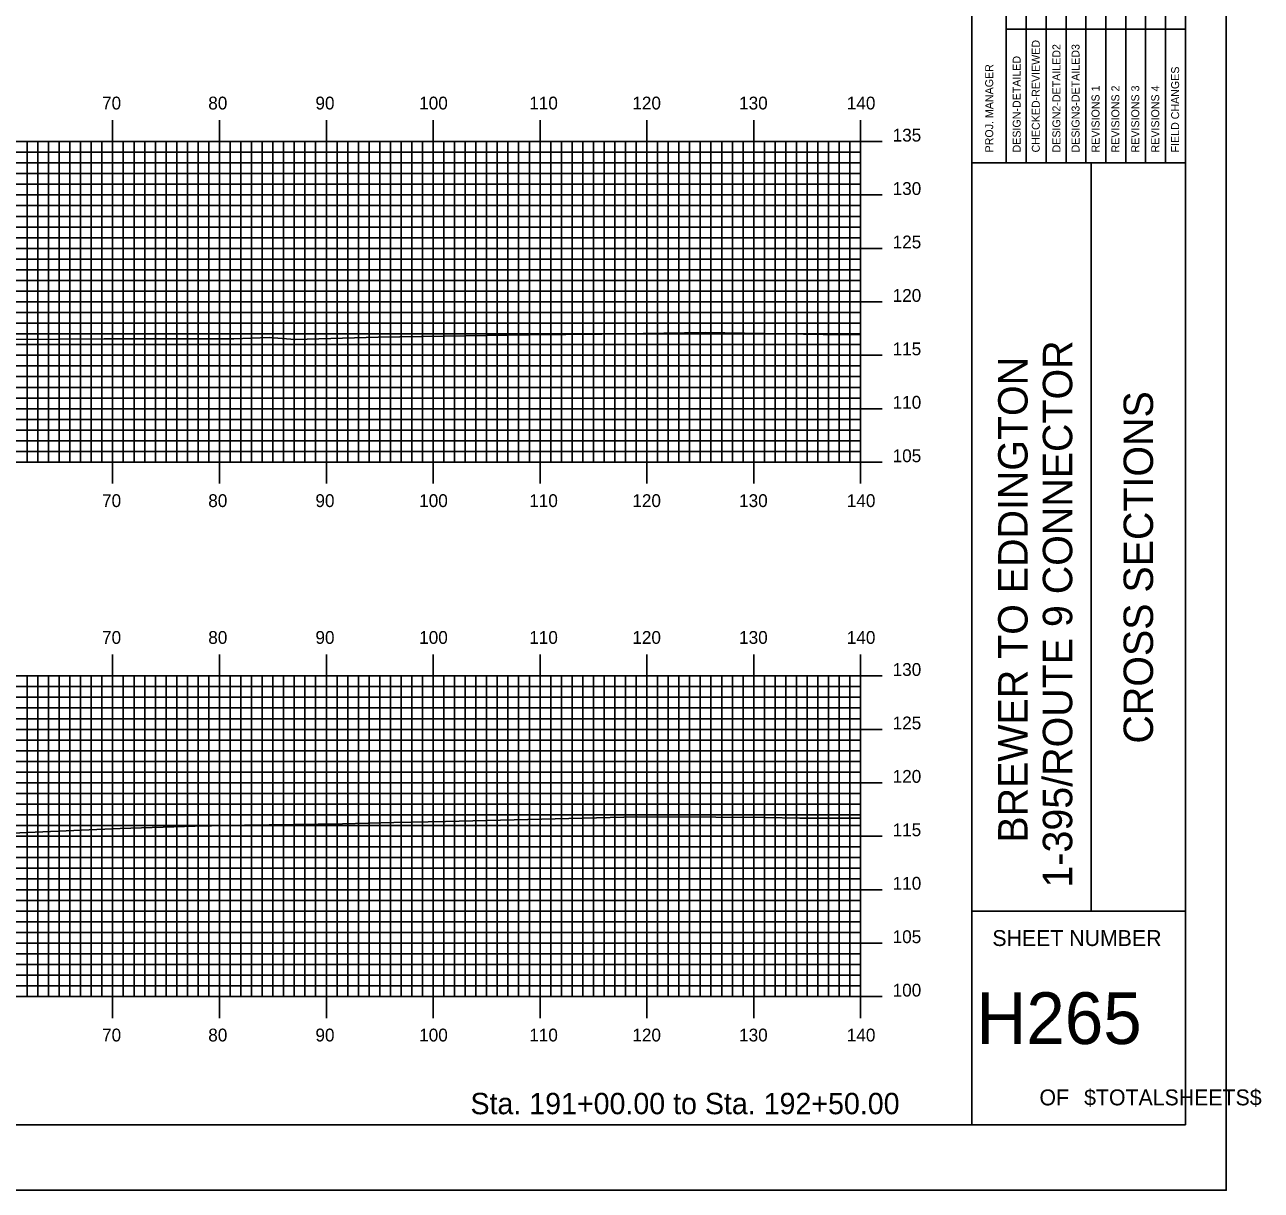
# Model space of a CAD drawing. Extents: x 1788550 to 1788893, y 442591 to 442811.
# Drawn here: x 1788777.4 to 1788893.1, y 442590.5 to 442699.6 of the extents above; entities that cross this region are included whole.
import ezdxf

# ---------------------------------------------------------------- set-up
doc = ezdxf.new("R2010")
doc.units = 0
for name, color, linetype in [('BORDER', 7, 'Continuous'), ('H_V ANNOTATION', 7, 'Continuous'), ('MAJOR', 7, 'Continuous'), ('MINOR', 7, 'Continuous'), ('PLOT BOUNDARY', 7, 'Continuous'), ('S_Roadway_Centerline', 7, 'Continuous')]:
    doc.layers.add(name, color=color, linetype=linetype)

msp = doc.modelspace()

# ---------------------------------------------------------------- linework, layer by layer
at = {"layer": 'BORDER'}
for p, q in [((1788866.04, 442596.67), (1788866.04, 442806.67)), ((1788866.04, 442686.67), (1788886.04, 442686.67)), ((1788877.23, 442616.67), (1788877.23, 442686.67)), ((1788866.04, 442616.67), (1788886.04, 442616.67))]:
    msp.add_line(p, q, dxfattribs=at)
msp.add_lwpolyline([(1788566.04, 442596.67), (1788886.04, 442596.67), (1788886.04, 442806.67), (1788566.04, 442806.67)], close=True, dxfattribs=at)
for points in [[(1788871.14, 442686.68), (1788871.14, 442721.67)], [(1788873, 442721.67), (1788873, 442686.68)], [(1788874.87, 442686.68), (1788874.87, 442721.67)], [(1788876.73, 442686.68), (1788876.73, 442721.67)], [(1788878.59, 442686.68), (1788878.59, 442721.67)], [(1788880.46, 442686.68), (1788880.46, 442721.67)], [(1788882.32, 442686.68), (1788882.32, 442721.67)], [(1788884.18, 442686.68), (1788884.18, 442721.67)], [(1788869.27, 442686.68), (1788869.27, 442720.26)], [(1788869.27, 442699.17), (1788886.04, 442699.17)]]:
    msp.add_lwpolyline(points, dxfattribs=at)
at = {"layer": 'MAJOR'}
for p, q in [((1788785.64, 442690.67), (1788785.64, 442688.67)), ((1788795.64, 442690.67), (1788795.64, 442688.67)), ((1788805.64, 442690.67), (1788805.64, 442688.67)), ((1788815.64, 442690.67), (1788815.64, 442688.67)), ((1788825.64, 442690.67), (1788825.64, 442688.67)), ((1788835.64, 442690.67), (1788835.64, 442688.67)), ((1788845.64, 442690.67), (1788845.64, 442688.67)), ((1788855.64, 442690.67), (1788855.64, 442688.67)), ((1788575.64, 442688.67), (1788855.64, 442688.67)), ((1788575.64, 442688.67), (1788855.64, 442688.67)), ((1788785.64, 442658.67), (1788785.64, 442688.67)), ((1788795.64, 442658.67), (1788795.64, 442688.67)), ((1788805.64, 442658.67), (1788805.64, 442688.67)), ((1788815.64, 442658.67), (1788815.64, 442688.67)), ((1788825.64, 442658.67), (1788825.64, 442688.67)), ((1788835.64, 442658.67), (1788835.64, 442688.67)), ((1788845.64, 442658.67), (1788845.64, 442688.67)), ((1788857.65, 442688.67), (1788853.64, 442688.67)), ((1788855.64, 442658.67), (1788855.64, 442688.67)), ((1788855.64, 442658.67), (1788855.64, 442688.67)), ((1788575.64, 442683.67), (1788855.64, 442683.67)), ((1788857.65, 442683.67), (1788853.64, 442683.67)), ((1788575.64, 442678.67), (1788855.64, 442678.67)), ((1788857.65, 442678.67), (1788853.64, 442678.67)), ((1788575.64, 442673.67), (1788855.64, 442673.67)), ((1788857.65, 442673.67), (1788853.64, 442673.67)), ((1788575.64, 442668.67), (1788855.64, 442668.67)), ((1788857.65, 442668.67), (1788853.64, 442668.67)), ((1788575.64, 442663.67), (1788855.64, 442663.67)), ((1788857.65, 442663.67), (1788853.64, 442663.67)), ((1788575.64, 442658.67), (1788855.64, 442658.67)), ((1788575.64, 442658.67), (1788855.64, 442658.67)), ((1788785.64, 442656.66), (1788785.64, 442658.67)), ((1788795.64, 442656.66), (1788795.64, 442658.67)), ((1788805.64, 442656.66), (1788805.64, 442658.67)), ((1788815.64, 442656.66), (1788815.64, 442658.67)), ((1788825.64, 442656.66), (1788825.64, 442658.67)), ((1788835.64, 442656.66), (1788835.64, 442658.67)), ((1788845.64, 442656.66), (1788845.64, 442658.67)), ((1788857.65, 442658.67), (1788853.64, 442658.67)), ((1788855.64, 442656.66), (1788855.64, 442658.67)), ((1788785.64, 442640.67), (1788785.64, 442638.67)), ((1788795.64, 442640.67), (1788795.64, 442638.67)), ((1788805.64, 442640.67), (1788805.64, 442638.67)), ((1788815.64, 442640.67), (1788815.64, 442638.67)), ((1788825.64, 442640.67), (1788825.64, 442638.67)), ((1788835.64, 442640.67), (1788835.64, 442638.67)), ((1788845.64, 442640.67), (1788845.64, 442638.67)), ((1788855.64, 442640.67), (1788855.64, 442638.67)), ((1788575.64, 442638.67), (1788855.64, 442638.67)), ((1788575.64, 442638.67), (1788855.64, 442638.67)), ((1788785.64, 442608.67), (1788785.64, 442638.67)), ((1788795.64, 442608.67), (1788795.64, 442638.67)), ((1788805.64, 442608.67), (1788805.64, 442638.67)), ((1788815.64, 442608.67), (1788815.64, 442638.67)), ((1788825.64, 442608.67), (1788825.64, 442638.67)), ((1788835.64, 442608.67), (1788835.64, 442638.67)), ((1788845.64, 442608.67), (1788845.64, 442638.67)), ((1788857.65, 442638.67), (1788853.64, 442638.67)), ((1788855.64, 442608.67), (1788855.64, 442638.67)), ((1788855.64, 442608.67), (1788855.64, 442638.67)), ((1788575.64, 442633.67), (1788855.64, 442633.67)), ((1788857.65, 442633.67), (1788853.64, 442633.67)), ((1788575.64, 442628.67), (1788855.64, 442628.67)), ((1788857.65, 442628.67), (1788853.64, 442628.67)), ((1788575.64, 442623.67), (1788855.64, 442623.67)), ((1788857.65, 442623.67), (1788853.64, 442623.67)), ((1788575.64, 442618.67), (1788855.64, 442618.67)), ((1788857.65, 442618.67), (1788853.64, 442618.67)), ((1788575.64, 442613.67), (1788855.64, 442613.67)), ((1788857.65, 442613.67), (1788853.64, 442613.67)), ((1788575.64, 442608.67), (1788855.64, 442608.67)), ((1788575.64, 442608.67), (1788855.64, 442608.67)), ((1788785.64, 442606.66), (1788785.64, 442608.67)), ((1788795.64, 442606.66), (1788795.64, 442608.67)), ((1788805.64, 442606.66), (1788805.64, 442608.67)), ((1788815.64, 442606.66), (1788815.64, 442608.67)), ((1788825.64, 442606.66), (1788825.64, 442608.67)), ((1788835.64, 442606.66), (1788835.64, 442608.67)), ((1788845.64, 442606.66), (1788845.64, 442608.67)), ((1788857.65, 442608.67), (1788853.64, 442608.67)), ((1788855.64, 442606.66), (1788855.64, 442608.67))]:
    msp.add_line(p, q, dxfattribs=at)
at = {"layer": 'MINOR'}
for p, q in [((1788777.64, 442658.67), (1788777.64, 442688.67)), ((1788778.64, 442658.67), (1788778.64, 442688.67)), ((1788779.64, 442658.67), (1788779.64, 442688.67)), ((1788780.64, 442658.67), (1788780.64, 442688.67)), ((1788781.64, 442658.67), (1788781.64, 442688.67)), ((1788782.64, 442658.67), (1788782.64, 442688.67)), ((1788783.64, 442658.67), (1788783.64, 442688.67)), ((1788784.64, 442658.67), (1788784.64, 442688.67)), ((1788786.64, 442658.67), (1788786.64, 442688.67)), ((1788787.64, 442658.67), (1788787.64, 442688.67)), ((1788788.64, 442658.67), (1788788.64, 442688.67)), ((1788789.64, 442658.67), (1788789.64, 442688.67)), ((1788790.64, 442658.67), (1788790.64, 442688.67)), ((1788791.64, 442658.67), (1788791.64, 442688.67)), ((1788792.64, 442658.67), (1788792.64, 442688.67)), ((1788793.64, 442658.67), (1788793.64, 442688.67)), ((1788794.64, 442658.67), (1788794.64, 442688.67)), ((1788796.64, 442658.67), (1788796.64, 442688.67)), ((1788797.64, 442658.67), (1788797.64, 442688.67)), ((1788798.64, 442658.67), (1788798.64, 442688.67)), ((1788799.64, 442658.67), (1788799.64, 442688.67)), ((1788800.64, 442658.67), (1788800.64, 442688.67)), ((1788801.64, 442658.67), (1788801.64, 442688.67)), ((1788802.64, 442658.67), (1788802.64, 442688.67)), ((1788803.64, 442658.67), (1788803.64, 442688.67)), ((1788804.64, 442658.67), (1788804.64, 442688.67)), ((1788806.64, 442658.67), (1788806.64, 442688.67)), ((1788807.64, 442658.67), (1788807.64, 442688.67)), ((1788808.64, 442658.67), (1788808.64, 442688.67)), ((1788809.64, 442658.67), (1788809.64, 442688.67)), ((1788810.64, 442658.67), (1788810.64, 442688.67)), ((1788811.64, 442658.67), (1788811.64, 442688.67)), ((1788812.64, 442658.67), (1788812.64, 442688.67)), ((1788813.64, 442658.67), (1788813.64, 442688.67)), ((1788814.64, 442658.67), (1788814.64, 442688.67)), ((1788816.64, 442658.67), (1788816.64, 442688.67)), ((1788817.64, 442658.67), (1788817.64, 442688.67)), ((1788818.64, 442658.67), (1788818.64, 442688.67)), ((1788819.64, 442658.67), (1788819.64, 442688.67)), ((1788820.64, 442658.67), (1788820.64, 442688.67)), ((1788821.64, 442658.67), (1788821.64, 442688.67)), ((1788822.64, 442658.67), (1788822.64, 442688.67)), ((1788823.64, 442658.67), (1788823.64, 442688.67)), ((1788824.64, 442658.67), (1788824.64, 442688.67)), ((1788826.64, 442658.67), (1788826.64, 442688.67)), ((1788827.64, 442658.67), (1788827.64, 442688.67)), ((1788828.64, 442658.67), (1788828.64, 442688.67)), ((1788829.64, 442658.67), (1788829.64, 442688.67)), ((1788830.64, 442658.67), (1788830.64, 442688.67)), ((1788831.64, 442658.67), (1788831.64, 442688.67)), ((1788832.64, 442658.67), (1788832.64, 442688.67)), ((1788833.64, 442658.67), (1788833.64, 442688.67)), ((1788834.64, 442658.67), (1788834.64, 442688.67)), ((1788836.64, 442658.67), (1788836.64, 442688.67)), ((1788837.64, 442658.67), (1788837.64, 442688.67)), ((1788838.64, 442658.67), (1788838.64, 442688.67)), ((1788839.64, 442658.67), (1788839.64, 442688.67)), ((1788840.64, 442658.67), (1788840.64, 442688.67)), ((1788841.64, 442658.67), (1788841.64, 442688.67)), ((1788842.64, 442658.67), (1788842.64, 442688.67)), ((1788843.64, 442658.67), (1788843.64, 442688.67)), ((1788844.64, 442658.67), (1788844.64, 442688.67)), ((1788846.64, 442658.67), (1788846.64, 442688.67)), ((1788847.64, 442658.67), (1788847.64, 442688.67)), ((1788848.64, 442658.67), (1788848.64, 442688.67)), ((1788849.64, 442658.67), (1788849.64, 442688.67)), ((1788850.64, 442658.67), (1788850.64, 442688.67)), ((1788851.64, 442658.67), (1788851.64, 442688.67)), ((1788852.64, 442658.67), (1788852.64, 442688.67)), ((1788853.64, 442658.67), (1788853.64, 442688.67)), ((1788854.64, 442658.67), (1788854.64, 442688.67)), ((1788575.64, 442687.67), (1788855.64, 442687.67)), ((1788855.64, 442687.67), (1788853.64, 442687.67)), ((1788575.64, 442686.67), (1788855.64, 442686.67)), ((1788855.64, 442686.67), (1788853.64, 442686.67)), ((1788575.64, 442685.67), (1788855.64, 442685.67)), ((1788855.64, 442685.67), (1788853.64, 442685.67)), ((1788575.64, 442684.67), (1788855.64, 442684.67)), ((1788855.64, 442684.67), (1788853.64, 442684.67)), ((1788575.64, 442682.67), (1788855.64, 442682.67)), ((1788855.64, 442682.67), (1788853.64, 442682.67)), ((1788575.64, 442681.67), (1788855.64, 442681.67)), ((1788855.64, 442681.67), (1788853.64, 442681.67)), ((1788575.64, 442680.67), (1788855.64, 442680.67)), ((1788855.64, 442680.67), (1788853.64, 442680.67)), ((1788575.64, 442679.67), (1788855.64, 442679.67)), ((1788855.64, 442679.67), (1788853.64, 442679.67)), ((1788575.64, 442677.67), (1788855.64, 442677.67)), ((1788855.64, 442677.67), (1788853.64, 442677.67)), ((1788575.64, 442676.67), (1788855.64, 442676.67)), ((1788855.64, 442676.67), (1788853.64, 442676.67)), ((1788575.64, 442675.67), (1788855.64, 442675.67)), ((1788575.64, 442674.67), (1788855.64, 442674.67)), ((1788855.64, 442675.67), (1788853.64, 442675.67)), ((1788855.64, 442674.67), (1788853.64, 442674.67)), ((1788575.64, 442672.67), (1788855.64, 442672.67)), ((1788855.64, 442672.67), (1788853.64, 442672.67)), ((1788575.64, 442671.67), (1788855.64, 442671.67)), ((1788855.64, 442671.67), (1788853.64, 442671.67)), ((1788575.64, 442670.67), (1788855.64, 442670.67)), ((1788855.64, 442670.67), (1788853.64, 442670.67)), ((1788575.64, 442669.67), (1788855.64, 442669.67)), ((1788855.64, 442669.67), (1788853.64, 442669.67)), ((1788575.64, 442667.67), (1788855.64, 442667.67)), ((1788855.64, 442667.67), (1788853.64, 442667.67)), ((1788575.64, 442666.67), (1788855.64, 442666.67)), ((1788855.64, 442666.67), (1788853.64, 442666.67)), ((1788575.64, 442665.67), (1788855.64, 442665.67)), ((1788855.64, 442665.67), (1788853.64, 442665.67)), ((1788575.64, 442664.67), (1788855.64, 442664.67)), ((1788855.64, 442664.67), (1788853.64, 442664.67)), ((1788575.64, 442662.67), (1788855.64, 442662.67)), ((1788855.64, 442662.67), (1788853.64, 442662.67)), ((1788575.64, 442661.67), (1788855.64, 442661.67)), ((1788575.64, 442660.67), (1788855.64, 442660.67)), ((1788855.64, 442661.67), (1788853.64, 442661.67)), ((1788855.64, 442660.67), (1788853.64, 442660.67)), ((1788575.64, 442659.67), (1788855.64, 442659.67)), ((1788855.64, 442659.67), (1788853.64, 442659.67)), ((1788777.64, 442608.67), (1788777.64, 442638.67)), ((1788778.64, 442608.67), (1788778.64, 442638.67)), ((1788779.64, 442608.67), (1788779.64, 442638.67)), ((1788780.64, 442608.67), (1788780.64, 442638.67)), ((1788781.64, 442608.67), (1788781.64, 442638.67)), ((1788782.64, 442608.67), (1788782.64, 442638.67)), ((1788783.64, 442608.67), (1788783.64, 442638.67)), ((1788784.64, 442608.67), (1788784.64, 442638.67)), ((1788786.64, 442608.67), (1788786.64, 442638.67)), ((1788787.64, 442608.67), (1788787.64, 442638.67)), ((1788788.64, 442608.67), (1788788.64, 442638.67)), ((1788789.64, 442608.67), (1788789.64, 442638.67)), ((1788790.64, 442608.67), (1788790.64, 442638.67)), ((1788791.64, 442608.67), (1788791.64, 442638.67)), ((1788792.64, 442608.67), (1788792.64, 442638.67)), ((1788793.64, 442608.67), (1788793.64, 442638.67)), ((1788794.64, 442608.67), (1788794.64, 442638.67)), ((1788796.64, 442608.67), (1788796.64, 442638.67)), ((1788797.64, 442608.67), (1788797.64, 442638.67)), ((1788798.64, 442608.67), (1788798.64, 442638.67)), ((1788799.64, 442608.67), (1788799.64, 442638.67)), ((1788800.64, 442608.67), (1788800.64, 442638.67)), ((1788801.64, 442608.67), (1788801.64, 442638.67)), ((1788802.64, 442608.67), (1788802.64, 442638.67)), ((1788803.64, 442608.67), (1788803.64, 442638.67)), ((1788804.64, 442608.67), (1788804.64, 442638.67)), ((1788806.64, 442608.67), (1788806.64, 442638.67)), ((1788807.64, 442608.67), (1788807.64, 442638.67)), ((1788808.64, 442608.67), (1788808.64, 442638.67)), ((1788809.64, 442608.67), (1788809.64, 442638.67)), ((1788810.64, 442608.67), (1788810.64, 442638.67)), ((1788811.64, 442608.67), (1788811.64, 442638.67)), ((1788812.64, 442608.67), (1788812.64, 442638.67)), ((1788813.64, 442608.67), (1788813.64, 442638.67)), ((1788814.64, 442608.67), (1788814.64, 442638.67)), ((1788816.64, 442608.67), (1788816.64, 442638.67)), ((1788817.64, 442608.67), (1788817.64, 442638.67)), ((1788818.64, 442608.67), (1788818.64, 442638.67)), ((1788819.64, 442608.67), (1788819.64, 442638.67)), ((1788820.64, 442608.67), (1788820.64, 442638.67)), ((1788821.64, 442608.67), (1788821.64, 442638.67)), ((1788822.64, 442608.67), (1788822.64, 442638.67)), ((1788823.64, 442608.67), (1788823.64, 442638.67)), ((1788824.64, 442608.67), (1788824.64, 442638.67)), ((1788826.64, 442608.67), (1788826.64, 442638.67)), ((1788827.64, 442608.67), (1788827.64, 442638.67)), ((1788828.64, 442608.67), (1788828.64, 442638.67)), ((1788829.64, 442608.67), (1788829.64, 442638.67)), ((1788830.64, 442608.67), (1788830.64, 442638.67)), ((1788831.64, 442608.67), (1788831.64, 442638.67)), ((1788832.64, 442608.67), (1788832.64, 442638.67)), ((1788833.64, 442608.67), (1788833.64, 442638.67)), ((1788834.64, 442608.67), (1788834.64, 442638.67)), ((1788836.64, 442608.67), (1788836.64, 442638.67)), ((1788837.64, 442608.67), (1788837.64, 442638.67)), ((1788838.64, 442608.67), (1788838.64, 442638.67)), ((1788839.64, 442608.67), (1788839.64, 442638.67)), ((1788840.64, 442608.67), (1788840.64, 442638.67)), ((1788841.64, 442608.67), (1788841.64, 442638.67)), ((1788842.64, 442608.67), (1788842.64, 442638.67)), ((1788843.64, 442608.67), (1788843.64, 442638.67)), ((1788844.64, 442608.67), (1788844.64, 442638.67)), ((1788846.64, 442608.67), (1788846.64, 442638.67)), ((1788847.64, 442608.67), (1788847.64, 442638.67)), ((1788848.64, 442608.67), (1788848.64, 442638.67)), ((1788849.64, 442608.67), (1788849.64, 442638.67)), ((1788850.64, 442608.67), (1788850.64, 442638.67)), ((1788851.64, 442608.67), (1788851.64, 442638.67)), ((1788852.64, 442608.67), (1788852.64, 442638.67)), ((1788853.64, 442608.67), (1788853.64, 442638.67)), ((1788854.64, 442608.67), (1788854.64, 442638.67)), ((1788575.64, 442637.67), (1788855.64, 442637.67)), ((1788855.64, 442637.67), (1788853.64, 442637.67)), ((1788575.64, 442636.67), (1788855.64, 442636.67)), ((1788855.64, 442636.67), (1788853.64, 442636.67)), ((1788575.64, 442635.67), (1788855.64, 442635.67)), ((1788855.64, 442635.67), (1788853.64, 442635.67)), ((1788575.64, 442634.67), (1788855.64, 442634.67)), ((1788855.64, 442634.67), (1788853.64, 442634.67)), ((1788575.64, 442632.67), (1788855.64, 442632.67)), ((1788855.64, 442632.67), (1788853.64, 442632.67)), ((1788575.64, 442631.67), (1788855.64, 442631.67)), ((1788575.64, 442630.67), (1788855.64, 442630.67)), ((1788855.64, 442631.67), (1788853.64, 442631.67)), ((1788855.64, 442630.67), (1788853.64, 442630.67)), ((1788575.64, 442629.67), (1788855.64, 442629.67)), ((1788855.64, 442629.67), (1788853.64, 442629.67)), ((1788575.64, 442627.67), (1788855.64, 442627.67)), ((1788855.64, 442627.67), (1788853.64, 442627.67)), ((1788575.64, 442626.67), (1788855.64, 442626.67)), ((1788855.64, 442626.67), (1788853.64, 442626.67)), ((1788575.64, 442625.67), (1788855.64, 442625.67)), ((1788855.64, 442625.67), (1788853.64, 442625.67)), ((1788575.64, 442624.67), (1788855.64, 442624.67)), ((1788855.64, 442624.67), (1788853.64, 442624.67)), ((1788575.64, 442622.67), (1788855.64, 442622.67)), ((1788855.64, 442622.67), (1788853.64, 442622.67)), ((1788575.64, 442621.67), (1788855.64, 442621.67)), ((1788855.64, 442621.67), (1788853.64, 442621.67)), ((1788575.64, 442620.67), (1788855.64, 442620.67)), ((1788855.64, 442620.67), (1788853.64, 442620.67)), ((1788575.64, 442619.67), (1788855.64, 442619.67)), ((1788855.64, 442619.67), (1788853.64, 442619.67)), ((1788575.64, 442617.67), (1788855.64, 442617.67)), ((1788575.64, 442616.67), (1788855.64, 442616.67)), ((1788855.64, 442617.67), (1788853.64, 442617.67)), ((1788855.64, 442616.67), (1788853.64, 442616.67)), ((1788575.64, 442615.67), (1788855.64, 442615.67)), ((1788855.64, 442615.67), (1788853.64, 442615.67)), ((1788575.64, 442614.67), (1788855.64, 442614.67)), ((1788855.64, 442614.67), (1788853.64, 442614.67)), ((1788575.64, 442612.67), (1788855.64, 442612.67)), ((1788855.64, 442612.67), (1788853.64, 442612.67)), ((1788575.64, 442611.67), (1788855.64, 442611.67)), ((1788855.64, 442611.67), (1788853.64, 442611.67)), ((1788575.64, 442610.67), (1788855.64, 442610.67)), ((1788855.64, 442610.67), (1788853.64, 442610.67)), ((1788575.64, 442609.67), (1788855.64, 442609.67)), ((1788855.64, 442609.67), (1788853.64, 442609.67))]:
    msp.add_line(p, q, dxfattribs=at)
at = {"layer": 'PLOT BOUNDARY'}
msp.add_lwpolyline([(1788549.86, 442590.55), (1788889.86, 442590.55), (1788889.86, 442810.55), (1788549.86, 442810.55)], close=True, dxfattribs=at)
at = {"layer": 'S_Roadway_Centerline'}
for points in [[(1788776.44, 442670.14), (1788784.84, 442670.21), (1788796.98, 442670.22), (1788800.28, 442670.34), (1788802.72, 442670.15), (1788810.49, 442670.36), (1788824.71, 442670.58), (1788831.43, 442670.66), (1788841.09, 442670.8), (1788852.14, 442670.61), (1788855.64, 442670.58)], [(1788774.75, 442623.9), (1788786.36, 442624.41), (1788793.37, 442624.62), (1788797.99, 442624.71), (1788807.14, 442624.82), (1788811.95, 442624.97), (1788816.8, 442625.06), (1788834.75, 442625.5), (1788842.1, 442625.44), (1788846.67, 442625.41), (1788849.95, 442625.37), (1788855.64, 442625.35)]]:
    msp.add_lwpolyline(points, dxfattribs=at)

# ---------------------------------------------------------------- texts
at = {"layer": 'BORDER'}
for s, height, p in [('CHECKED-REVIEWED', 0.7455, (1788872.41, 442687.65)), ('DESIGN2-DETAILED2', 0.7455, (1788874.34, 442687.65)), ('DESIGN3-DETAILED3', 0.7455, (1788876.13, 442687.65)), ('DESIGN-DETAILED', 0.7455, (1788870.62, 442687.65)), ('PROJ. MANAGER', 0.7455, (1788868.05, 442687.65)), ('FIELD CHANGES', 0.7455, (1788885.45, 442687.65)), ('REVISIONS 1', 0.7455, (1788878, 442687.65)), ('REVISIONS 2', 0.7455, (1788879.86, 442687.65)), ('REVISIONS 3', 0.7455, (1788881.72, 442687.65)), ('REVISIONS 4', 0.7455, (1788883.59, 442687.65)), ('1-395/ROUTE 9 CONNECTOR', 2.7557, (1788875.45, 442618.87)), ('BREWER TO EDDINGTON', 2.7557, (1788871.27, 442623.07)), ('CROSS SECTIONS', 2.7557, (1788883.01, 442632.34))]:
    msp.add_text(s, height=height, rotation=90, dxfattribs=at).set_placement(p)
for s, height, p in [('SHEET NUMBER', 1.4905, (1788867.97, 442613.4)), ('H265', 4.839, (1788866.48, 442604.23)), ('OF', 1.491, (1788872.38, 442598.49)), ('$TOTALSHEETS$', 1.4905, (1788876.56, 442598.49))]:
    msp.add_text(s, height=height, dxfattribs=at).set_placement(p)
at = {"layer": 'H_V ANNOTATION'}
for s, height, p in [('70', 1.2, (1788784.65, 442691.67)), ('80', 1.2, (1788794.59, 442691.67)), ('90', 1.2, (1788804.62, 442691.67)), ('100', 1.2, (1788814.33, 442691.67)), ('110', 1.2, (1788824.63, 442691.67)), ('120', 1.2, (1788834.28, 442691.67)), ('130', 1.2, (1788844.27, 442691.67)), ('140', 1.2, (1788854.35, 442691.67)), ('135', 1.2, (1788858.64, 442688.67)), ('130', 1.2, (1788858.64, 442683.67)), ('125', 1.2, (1788858.64, 442678.67)), ('120', 1.2, (1788858.64, 442673.67)), ('115', 1.2, (1788858.64, 442668.67)), ('110', 1.2, (1788858.64, 442663.67)), ('105', 1.2, (1788858.64, 442658.67)), ('70', 1.2, (1788784.65, 442654.47)), ('80', 1.2, (1788794.59, 442654.47)), ('90', 1.2, (1788804.62, 442654.47)), ('100', 1.2, (1788814.33, 442654.47)), ('110', 1.2, (1788824.63, 442654.47)), ('120', 1.2, (1788834.28, 442654.47)), ('130', 1.2, (1788844.27, 442654.47)), ('140', 1.2, (1788854.35, 442654.47)), ('70', 1.2, (1788784.65, 442641.67)), ('80', 1.2, (1788794.59, 442641.67)), ('90', 1.2, (1788804.62, 442641.67)), ('100', 1.2, (1788814.33, 442641.67)), ('110', 1.2, (1788824.63, 442641.67)), ('120', 1.2, (1788834.28, 442641.67)), ('130', 1.2, (1788844.27, 442641.67)), ('140', 1.2, (1788854.35, 442641.67)), ('130', 1.2, (1788858.64, 442638.67)), ('125', 1.2, (1788858.64, 442633.67)), ('120', 1.2, (1788858.64, 442628.67)), ('115', 1.2, (1788858.64, 442623.67)), ('110', 1.2, (1788858.64, 442618.67)), ('105', 1.2, (1788858.64, 442613.67)), ('100', 1.2, (1788858.64, 442608.67)), ('70', 1.2, (1788784.65, 442604.47)), ('80', 1.2, (1788794.59, 442604.47)), ('90', 1.2, (1788804.62, 442604.47)), ('100', 1.2, (1788814.33, 442604.47)), ('110', 1.2, (1788824.63, 442604.47)), ('120', 1.2, (1788834.28, 442604.47)), ('130', 1.2, (1788844.27, 442604.47)), ('140', 1.2, (1788854.35, 442604.47)), ('Sta. 191+00.00 to Sta. 192+50.00', 2.0004, (1788819.13, 442597.66))]:
    msp.add_text(s, height=height, dxfattribs=at).set_placement(p)

doc.saveas('drawing.dxf')
